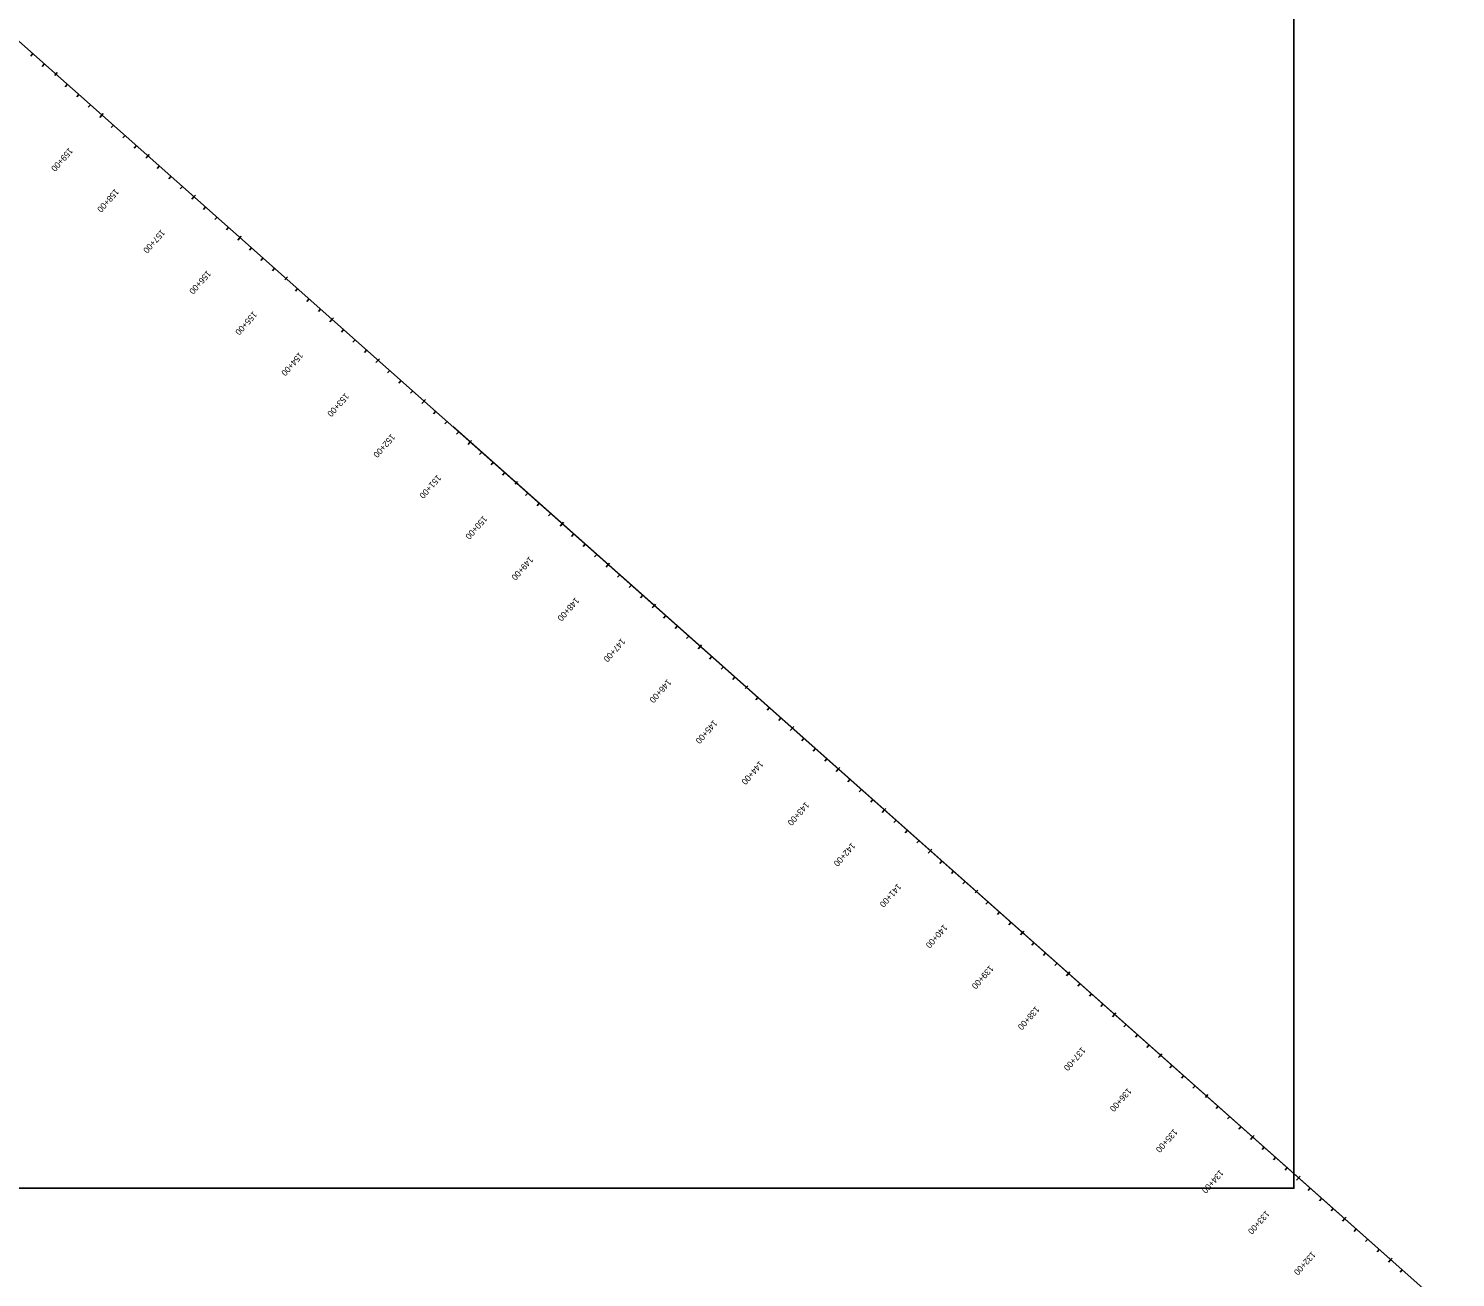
# Model space of a CAD drawing. Extents: x 5226274 to 5237131, y 3641705 to 3648830.
# Drawn here: x 5232512 to 5234830, y 3643826 to 3645855 of the extents above; entities that cross this region are included whole.
import ezdxf

# ---------------------------------------------------------------- set-up
doc = ezdxf.new("R2010")
doc.units = 0
for name, color, linetype in [('Alignment', 7, 'Continuous'), ('TextAlignmentLrg', 7, 'Continuous'), ('TextAlignmentSml', 7, 'Continuous'), ('TextNonPlot', 7, 'Continuous')]:
    doc.layers.add(name, color=color, linetype=linetype)

msp = doc.modelspace()

# ---------------------------------------------------------------- linework, layer by layer
at = {"layer": 'Alignment'}
for q in [(5232496.9, 3645834.9), (5233201.4, 3645209.2)]:
    msp.add_line((5237043, 3641797.1), q, dxfattribs=at)
at = {"layer": 'TextAlignmentLrg'}
for p, q in [((5232555, 3645779.2), (5232559.1, 3645783.8)), ((5232631.8, 3645715.1), (5232628.2, 3645711)), ((5232706.6, 3645648.7), (5232702.9, 3645644.6)), ((5232781.3, 3645582.3), (5232777.7, 3645578.2)), ((5232856.1, 3645515.9), (5232852.5, 3645511.8)), ((5232928.8, 3645447.2), (5232932.9, 3645451.8)), ((5233005.6, 3645383.1), (5233002, 3645379)), ((5233080.4, 3645316.7), (5233076.8, 3645312.6)), ((5233155.2, 3645250.3), (5233151.5, 3645246.2)), ((5233229.9, 3645183.9), (5233226.3, 3645179.8)), ((5233302.7, 3645115.2), (5233306.7, 3645119.7)), ((5233379.5, 3645051), (5233375.8, 3645047)), ((5233454.2, 3644984.6), (5233450.6, 3644980.6)), ((5233529, 3644918.2), (5233525.4, 3644914.1)), ((5233603.8, 3644851.8), (5233600.1, 3644847.7)), ((5233676.5, 3644783.1), (5233680.6, 3644787.7)), ((5233753.3, 3644719), (5233749.7, 3644714.9)), ((5233828.1, 3644652.6), (5233824.4, 3644648.5)), ((5233902.8, 3644586.2), (5233899.2, 3644582.1)), ((5233977.6, 3644519.8), (5233974, 3644515.7)), ((5234050.3, 3644451.1), (5234054.4, 3644455.7)), ((5234127.1, 3644387), (5234123.5, 3644382.9)), ((5234201.9, 3644320.6), (5234198.3, 3644316.5)), ((5234276.7, 3644254.2), (5234273, 3644250.1)), ((5234351.4, 3644187.7), (5234347.8, 3644183.7)), ((5234424.2, 3644119), (5234428.2, 3644123.6)), ((5234501, 3644054.9), (5234497.3, 3644050.8)), ((5234575.7, 3643988.5), (5234572.1, 3643984.4)), ((5234650.5, 3643922.1), (5234646.9, 3643918)), ((5234725.3, 3643855.7), (5234721.6, 3643851.6))]:
    msp.add_line(p, q, dxfattribs=at)
at = {"layer": 'TextAlignmentSml'}
for p, q in [((5232519.6, 3645814.7), (5232516, 3645810.6)), ((5232538.3, 3645798.1), (5232534.7, 3645794)), ((5232555, 3645779.2), (5232559.1, 3645783.8)), ((5232575.7, 3645764.9), (5232572.1, 3645760.8)), ((5232594.4, 3645748.3), (5232590.8, 3645744.2)), ((5232613.1, 3645731.7), (5232609.5, 3645727.6)), ((5232629.8, 3645712.8), (5232633.8, 3645717.4)), ((5232650.5, 3645698.5), (5232646.9, 3645694.4)), ((5232669.2, 3645681.9), (5232665.6, 3645677.8)), ((5232687.9, 3645665.3), (5232684.2, 3645661.2)), ((5232704.5, 3645646.4), (5232708.6, 3645651)), ((5232725.3, 3645632.1), (5232721.6, 3645628)), ((5232743.9, 3645615.5), (5232740.3, 3645611.4)), ((5232762.6, 3645598.9), (5232759, 3645594.8)), ((5232779.3, 3645580), (5232783.4, 3645584.6)), ((5232800, 3645565.7), (5232796.4, 3645561.6)), ((5232818.7, 3645549.1), (5232815.1, 3645545)), ((5232837.4, 3645532.5), (5232833.8, 3645528.4)), ((5232854.1, 3645513.6), (5232858.1, 3645518.2)), ((5232874.8, 3645499.3), (5232871.2, 3645495.2)), ((5232893.5, 3645482.7), (5232889.9, 3645478.6)), ((5232912.2, 3645466.1), (5232908.5, 3645462)), ((5232928.8, 3645447.2), (5232932.9, 3645451.8)), ((5232949.6, 3645432.9), (5232945.9, 3645428.8)), ((5232968.2, 3645416.3), (5232964.6, 3645412.2)), ((5232986.9, 3645399.7), (5232983.3, 3645395.6)), ((5233003.6, 3645380.8), (5233007.7, 3645385.4)), ((5233024.3, 3645366.5), (5233020.7, 3645362.4)), ((5233043, 3645349.9), (5233039.4, 3645345.8)), ((5233061.7, 3645333.3), (5233058.1, 3645329.2)), ((5233078.4, 3645314.4), (5233082.4, 3645319)), ((5233099.1, 3645300.1), (5233095.5, 3645296)), ((5233117.8, 3645283.5), (5233114.2, 3645279.4)), ((5233136.5, 3645266.9), (5233132.8, 3645262.8)), ((5233153.1, 3645248), (5233157.2, 3645252.6)), ((5233173.9, 3645233.7), (5233170.2, 3645229.6)), ((5233192.5, 3645217.1), (5233188.9, 3645213)), ((5233211.2, 3645200.5), (5233207.6, 3645196.4)), ((5233227.9, 3645181.6), (5233232, 3645186.1)), ((5233248.6, 3645167.3), (5233245, 3645163.2)), ((5233267.3, 3645150.7), (5233263.7, 3645146.6)), ((5233286, 3645134.1), (5233282.4, 3645130)), ((5233302.7, 3645115.2), (5233306.7, 3645119.7)), ((5233323.4, 3645100.8), (5233319.8, 3645096.8)), ((5233342.1, 3645084.2), (5233338.5, 3645080.2)), ((5233360.8, 3645067.6), (5233357.1, 3645063.6)), ((5233377.4, 3645048.8), (5233381.5, 3645053.3)), ((5233398.2, 3645034.4), (5233394.5, 3645030.4)), ((5233416.8, 3645017.8), (5233413.2, 3645013.8)), ((5233435.5, 3645001.2), (5233431.9, 3644997.2)), ((5233452.2, 3644982.3), (5233456.3, 3644986.9)), ((5233472.9, 3644968), (5233469.3, 3644964)), ((5233491.6, 3644951.4), (5233488, 3644947.3)), ((5233510.3, 3644934.8), (5233506.7, 3644930.7)), ((5233527, 3644915.9), (5233531, 3644920.5)), ((5233547.7, 3644901.6), (5233544.1, 3644897.5)), ((5233566.4, 3644885), (5233562.8, 3644880.9)), ((5233585.1, 3644868.4), (5233581.4, 3644864.3)), ((5233601.7, 3644849.5), (5233605.8, 3644854.1)), ((5233622.5, 3644835.2), (5233618.8, 3644831.1)), ((5233641.1, 3644818.6), (5233637.5, 3644814.5)), ((5233659.8, 3644802), (5233656.2, 3644797.9)), ((5233676.5, 3644783.1), (5233680.6, 3644787.7)), ((5233697.2, 3644768.8), (5233693.6, 3644764.7)), ((5233715.9, 3644752.2), (5233712.3, 3644748.1)), ((5233734.6, 3644735.6), (5233731, 3644731.5)), ((5233751.3, 3644716.7), (5233755.3, 3644721.3)), ((5233772, 3644702.4), (5233768.4, 3644698.3)), ((5233790.7, 3644685.8), (5233787.1, 3644681.7)), ((5233809.4, 3644669.2), (5233805.7, 3644665.1)), ((5233826, 3644650.3), (5233830.1, 3644654.9)), ((5233846.8, 3644636), (5233843.1, 3644631.9)), ((5233865.4, 3644619.4), (5233861.8, 3644615.3)), ((5233884.1, 3644602.8), (5233880.5, 3644598.7)), ((5233900.8, 3644583.9), (5233904.9, 3644588.5)), ((5233921.5, 3644569.6), (5233917.9, 3644565.5)), ((5233940.2, 3644553), (5233936.6, 3644548.9)), ((5233958.9, 3644536.4), (5233955.3, 3644532.3)), ((5233975.6, 3644517.5), (5233979.6, 3644522.1)), ((5233996.3, 3644503.2), (5233992.7, 3644499.1)), ((5234015, 3644486.6), (5234011.4, 3644482.5)), ((5234033.7, 3644470), (5234030, 3644465.9)), ((5234050.3, 3644451.1), (5234054.4, 3644455.7)), ((5234071.1, 3644436.8), (5234067.4, 3644432.7)), ((5234089.7, 3644420.2), (5234086.1, 3644416.1)), ((5234108.4, 3644403.6), (5234104.8, 3644399.5)), ((5234125.1, 3644384.7), (5234129.2, 3644389.3)), ((5234145.8, 3644370.4), (5234142.2, 3644366.3)), ((5234164.5, 3644353.8), (5234160.9, 3644349.7)), ((5234183.2, 3644337.2), (5234179.6, 3644333.1)), ((5234199.9, 3644318.3), (5234203.9, 3644322.8)), ((5234220.6, 3644304), (5234217, 3644299.9)), ((5234239.3, 3644287.4), (5234235.6, 3644283.3)), ((5234258, 3644270.8), (5234254.3, 3644266.7)), ((5234274.6, 3644251.9), (5234278.7, 3644256.4)), ((5234295.4, 3644237.5), (5234291.7, 3644233.5)), ((5234314, 3644220.9), (5234310.4, 3644216.9)), ((5234332.7, 3644204.3), (5234329.1, 3644200.3)), ((5234349.4, 3644185.5), (5234353.5, 3644190)), ((5234370.1, 3644171.1), (5234366.5, 3644167.1)), ((5234388.8, 3644154.5), (5234385.2, 3644150.5)), ((5234407.5, 3644137.9), (5234403.9, 3644133.9)), ((5234424.2, 3644119), (5234428.2, 3644123.6)), ((5234444.9, 3644104.7), (5234441.3, 3644100.7)), ((5234463.6, 3644088.1), (5234459.9, 3644084)), ((5234482.3, 3644071.5), (5234478.6, 3644067.4)), ((5234498.9, 3644052.6), (5234503, 3644057.2)), ((5234519.6, 3644038.3), (5234516, 3644034.2)), ((5234538.3, 3644021.7), (5234534.7, 3644017.6)), ((5234557, 3644005.1), (5234553.4, 3644001)), ((5234573.7, 3643986.2), (5234577.8, 3643990.8)), ((5234594.4, 3643971.9), (5234590.8, 3643967.8)), ((5234613.1, 3643955.3), (5234609.5, 3643951.2)), ((5234631.8, 3643938.7), (5234628.2, 3643934.6)), ((5234648.5, 3643919.8), (5234652.5, 3643924.4)), ((5234669.2, 3643905.5), (5234665.6, 3643901.4)), ((5234687.9, 3643888.9), (5234684.2, 3643884.8)), ((5234706.6, 3643872.3), (5234702.9, 3643868.2)), ((5234723.2, 3643853.4), (5234727.3, 3643858)), ((5234743.9, 3643839.1), (5234740.3, 3643835))]:
    msp.add_line(p, q, dxfattribs=at)
at = {"layer": 'TextNonPlot'}
msp.add_lwpolyline([(5229515.6, 3647961.2), (5234567.8, 3647961.2), (5234567.8, 3643971.3), (5229515.6, 3643971.3)], close=True, dxfattribs=at)

# ---------------------------------------------------------------- texts
at = {"layer": 'TextAlignmentLrg'}
for s, p in [('155+00', (5232877.3, 3645396.7)), ('150+00', (5233251.1, 3645064.7)), ('145+00', (5233625, 3644732.7)), ('140+00', (5233998.8, 3644400.6)), ('135+00', (5234372.6, 3644068.6))]:
    msp.add_text(s, height=10.02, rotation=228.3884, dxfattribs=at).set_placement(p)
at = {"layer": 'TextAlignmentSml'}
for s, p in [('159+00', (5232578.2, 3645662.4)), ('158+00', (5232653, 3645596)), ('157+00', (5232727.8, 3645529.6)), ('156+00', (5232802.5, 3645463.1)), ('155+00', (5232877.3, 3645396.7)), ('154+00', (5232952.1, 3645330.3)), ('153+00', (5233026.8, 3645263.9)), ('152+00', (5233101.6, 3645197.5)), ('151+00', (5233176.4, 3645131.1)), ('150+00', (5233251.1, 3645064.7)), ('149+00', (5233325.9, 3644998.3)), ('148+00', (5233400.7, 3644931.9)), ('147+00', (5233475.4, 3644865.5)), ('146+00', (5233550.2, 3644799.1)), ('145+00', (5233625, 3644732.7)), ('144+00', (5233699.7, 3644666.3)), ('143+00', (5233774.5, 3644599.8)), ('142+00', (5233849.3, 3644533.4)), ('141+00', (5233924, 3644467)), ('140+00', (5233998.8, 3644400.6)), ('139+00', (5234073.6, 3644334.2)), ('138+00', (5234148.3, 3644267.8)), ('137+00', (5234223.1, 3644201.4)), ('136+00', (5234297.9, 3644135)), ('135+00', (5234372.6, 3644068.6)), ('134+00', (5234447.4, 3644002.2)), ('133+00', (5234522.2, 3643935.8)), ('132+00', (5234596.9, 3643869.4))]:
    msp.add_text(s, height=10.02, rotation=228.3884, dxfattribs=at).set_placement(p)

doc.saveas('drawing.dxf')
